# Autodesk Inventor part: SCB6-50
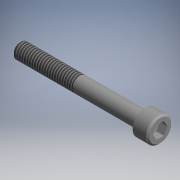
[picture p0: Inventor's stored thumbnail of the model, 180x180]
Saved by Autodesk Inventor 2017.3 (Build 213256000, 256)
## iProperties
Part Number: SCB6-50
Material: Generic
Catalog Web Link: www.cadenas.de
Description: SCB-Hexagon Socket Head Cap Screws - Stainless Steel
Vendor: MISUMI
Document SubType Name: Modeling
Designer: partserver
Manufacturer: MISUMI
Mass: 1.80564 g
Surface Area: 13.206 cm^2
Volume: 1.80564 cm^3
Density: 1 g/cm^3
Appearance: PSOLRGB-175-175-175
Category: PARTsolutions
Company: MISUMI
Title: SCB6-50
Author: Cadenas PARTsolutions
Comments: Hexagon Socket Head Cap Screws - Stainless Steel
PSOL_IDENT_0: {$CADENAS_DATA\23d-libs\misumi\metric\27_screws_nuts\scb_fa.prj},154 {VTYP=3D},{NB=SCB6-50},{LINA=SC
PSOL_IDENT_1: B6-50},{NN=SCB},{DATE=03.06.2021 03:35:43},{GEOMDATE=23.02.2012 00:00:00},{VERSION=},{LINEID=120},{W
PSOL_IDENT_2: BVAR=L},{WBNUMERIC=L}  {NB=SCB6-50},{LINA=SCB6-50},{KT=DUMMY},{PN=SCB6-50},{MAT=SUSXM7(30430 Stainle
PSOL_IDENT_3: ss Steel)},{SC=A2-70},{M=6},{L=50},{LL=24},{L1=24},{TYPE=SCB},{M1=6.0},{L0=8,10,12,14,15,16,18,20,22
PSOL_IDENT_4: ,25,30,35,40,45,50,55,60,65,70},{MP=6x1},{P=1},{A=10.0},{E=6.0},{B=5.0},{V=0.60}
NB: SCB6-50
NN: SCB
NT: Hexagon Socket Head Cap Screws - Stainless Steel
NBSYN: $PN.
LINA: SCB6-50
CATALOG: Misumi
PN: SCB6-50
MAT: 302HQ Stainless Steel
SC: A2-70
M: 6
L: 50
LL: 24
MP: 6x1
A: 10
E: 6
B: 5
SUPPLIER: MISUMI
ARTICLENO: SCB6-50
BOMINFO: SCB6-50
CREATOR: CADENAS GmbH
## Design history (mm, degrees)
sketch "Sketch_2"
  geometry: L1 (50, 0)-(-6, 0); L2 (-6, 0)-(-6, 4.333); L3 (-6, 4.333)-(-5.333, 5); L4 (-5.333, 5)-(0, 5); L5 (0, 5)-(0, 3); L6 (0, 3)-(49.386, 3); L7 (49.386, 3)-(50, 2.386); L8 (50, 2.386)-(50, 0); L9 (50, 0)-(-6, 0)
  constraints: 18 end point
revolve "Revolution1" sketch "Sketch_2" stored, may be unused: angle "d0" = 360 deg
thread "Thread1" dims "d1" = 23.3865, "d2" = 0
sketch "Sketch2"
  geometry: 1 further point
hole "Hole1" sketch "Sketch2" at (0, 0) diameter "d3" = 5; stored, may be unused: countersink angle "d7" = 90 deg, drill point angle "d9" = 150 deg; dims "d4" = 6, "d5" = 4, "d6" = 2, "d8" = 3
sketch "Sketch_3"
  geometry: L1 (-2.5, -1.443)-(0, -2.887); L2 (0, -2.887)-(2.5, -1.443); L3 (2.5, -1.443)-(2.5, 1.443); L4 (2.5, 1.443)-(0, 2.887); L5 (0, 2.887)-(-2.5, 1.443); L6 (-2.5, 1.443)-(-2.5, -1.443)
  constraints: 12 end point
extrude "Extrusion1" cut sketch "Sketch_3" distance "d10" = 3; taper "d11" = 0 deg
node "bolt_XY"
node "bolt_YZ"
node "bolt_ZX"
node "bolt_X"
node "bolt_Y"
node "bolt_Z"
node "bolt_Center"
node "nut_XY"
node "nut_YZ"
node "nut_ZX"
node "nut_X"
node "nut_Y"
node "nut_Z"
node "nut_Center"
body "Solid1"
other parameters: "d12" = 0, "d13" = 0
